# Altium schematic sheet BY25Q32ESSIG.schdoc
size 127 x 101 mm
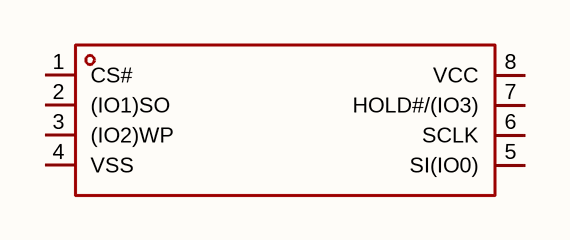
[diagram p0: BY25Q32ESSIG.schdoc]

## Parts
U?  by25q32essig  [SOP-8_L5.3-W5.2-P1.27-LS7.9-BL]  (value not drawn)

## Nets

Not connected (* = marked no-connect by the designer): U? 1(CS#) 2((IO1)SO) 3((IO2)WP) 4(VSS) 5(SI(IO0)) 6(SCLK) 7(HOLD#/(IO3)) 8(VCC)

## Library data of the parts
U? = by25q32essig: 接口类型:SPI;存储容量:-;时钟频率(fc):120MHz;; Manufacturer: BOYAMICRO(博雅); AddInBom: yes; ModelId: b3bace262c53465a9e6115a2e0c7b3cc; ModelTransform: 205.905,311.023,0,0,0,0,0,0,0; Interface: SPI; Clock Frequency: 120MHz; Voltage - Supply: 2.7V~3.6V; Program / Erase Cycles: 100000次; Page Programming Time (Tpp): 450us; Data Retention - TDR (Year): 20年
